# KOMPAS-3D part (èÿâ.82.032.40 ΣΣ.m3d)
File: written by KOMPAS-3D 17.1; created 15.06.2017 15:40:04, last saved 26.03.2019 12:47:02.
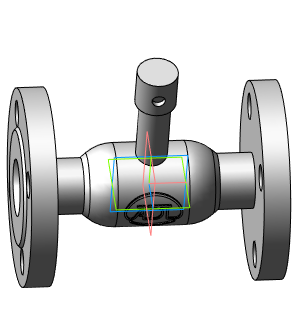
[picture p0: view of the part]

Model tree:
1. Операция без истории:2  (labels: Сталь 20  ГОСТ 1050-88)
